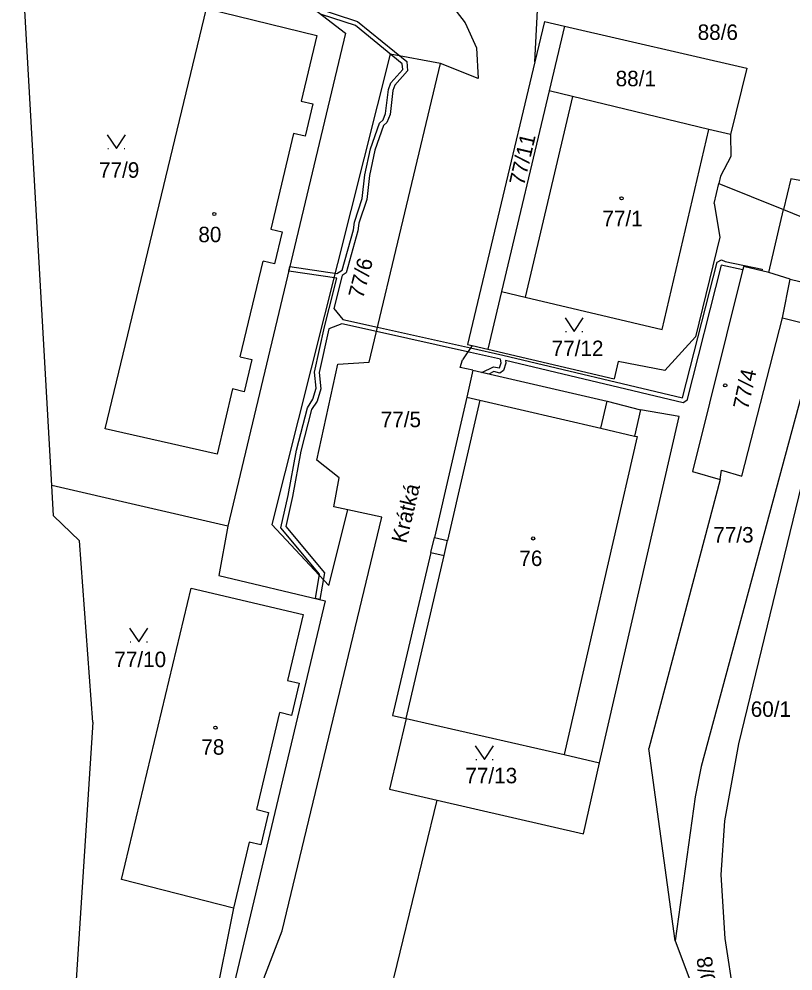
# Model space of a CAD drawing. Extents: x -670359 to -668019, y -978807 to -976674.
# Drawn here: x -670340.4 to -670255.4, y -977711.4 to -977606.8 of the extents above; entities that cross this region are included whole.
import ezdxf

# ---------------------------------------------------------------- set-up
doc = ezdxf.new("R2010")
doc.units = 0
for name, color, linetype in [('Hranice kat_území', 7, 'Continuous'), ('Hranice parcel', 7, 'Continuous'), ('Parcelní čísla', 7, 'Continuous'), ('Pop  PČ popisy', 7, 'Continuous'), ('Vnitřní kresba', 7, 'Continuous'), ('Věcná břemena k části', 7, 'Continuous'), ('Značky budov', 7, 'Continuous'), ('Značky kultur', 7, 'Continuous')]:
    doc.layers.add(name, color=color, linetype=linetype)

msp = doc.modelspace()

# ---------------------------------------------------------------- linework, layer by layer
at = {"layer": 'Hranice kat_území'}
for points in [[(-670336.85, -977658.05), (-670340.44, -977594.85)], [(-670336.66, -977661.37), (-670336.85, -977658.05)], [(-670333.8, -977664.11), (-670336.66, -977661.37)], [(-670332.34, -977684.03), (-670333.8, -977664.11)], [(-670332.34, -977684.03), (-670334.21, -977712.94)]]:
    msp.add_lwpolyline(points, dxfattribs=at)
at = {"layer": 'Hranice parcel'}
for points in [[(-670283.76, -977611.51), (-670283.19, -977600.11)], [(-670311.4, -977603.07), (-670304.57, -977608.35)], [(-670293.42, -977604.61), (-670291.41, -977607.22)], [(-670330.99, -977651.81), (-670319.86, -977605.66)], [(-670319.86, -977605.66), (-670307.72, -977608.63)], [(-670282.7, -977607.08), (-670283.76, -977611.51)], [(-670282.7, -977607.08), (-670280.5, -977607.59)], [(-670291.41, -977607.22), (-670290.19, -977609.96)], [(-670280.5, -977607.59), (-670282.2, -977614.71)], [(-670280.5, -977607.59), (-670260.47, -977612.22)], [(-670304.57, -977608.35), (-670317.49, -977662.51)], [(-670307.72, -977608.63), (-670309.43, -977615.83)], [(-670290.19, -977609.96), (-670289.99, -977613.35)], [(-670301.97, -977644.5), (-670294.13, -977611.68)], [(-670289.99, -977613.35), (-670294.13, -977611.68)], [(-670283.76, -977611.51), (-670291.18, -977642.54)], [(-670260.47, -977612.22), (-670262.27, -977619.5)], [(-670282.2, -977614.71), (-670287.43, -977636.75)], [(-670279.63, -977615.33), (-670282.2, -977614.71)], [(-670264.66, -977618.94), (-670279.63, -977615.33)], [(-670309.43, -977615.83), (-670308.17, -977616.13)], [(-670308.17, -977616.13), (-670309.02, -977619.68)], [(-670310.28, -977619.38), (-670312.79, -977629.87)], [(-670309.02, -977619.68), (-670310.28, -977619.38)], [(-670269.78, -977640.91), (-670264.66, -977618.94)], [(-670262.27, -977619.5), (-670264.66, -977618.94)], [(-670262.27, -977619.5), (-670262.23, -977621.89)], [(-670262.23, -977621.89), (-670263.37, -977624.05)], [(-670264.06, -977627.06), (-670263.56, -977624.87)], [(-670263.37, -977624.05), (-670263.56, -977624.87)], [(-670263.56, -977624.87), (-670256.44, -977627.73)], [(-670264.06, -977627.06), (-670263.45, -977630.78)], [(-670258.05, -977634.65), (-670256.44, -977627.73)], [(-670256.44, -977627.73), (-670253.29, -977629)], [(-670312.79, -977629.87), (-670311.52, -977630.18)], [(-670311.52, -977630.18), (-670312.36, -977633.7)], [(-670263.45, -977630.78), (-670266.1, -977641.73)], [(-670316.13, -977643.91), (-670313.63, -977633.4)], [(-670312.36, -977633.7), (-670313.63, -977633.4)], [(-670260.84, -977633.99), (-670266.45, -977656.5)], [(-670258.05, -977634.65), (-670260.84, -977633.99)], [(-670255.73, -977635.38), (-670258.05, -977634.65)], [(-670256.56, -977639.61), (-670255.73, -977635.38)], [(-670287.43, -977636.75), (-670288.94, -977643.07)], [(-670287.43, -977636.75), (-670284.82, -977637.36)], [(-670284.82, -977637.36), (-670269.78, -977640.91)], [(-670261.01, -977657.02), (-670256.56, -977639.61)], [(-670252.45, -977640.66), (-670265.48, -977688.9)], [(-670228.39, -977798.54), (-670235.68, -977780.88), (-670248.21, -977752.09), (-670257.66, -977728.06), (-670261.88, -977714.27), (-670262.87, -977707.81), (-670263.3, -977700.83), (-670262.9, -977694.87), (-670261.36, -977686.41), (-670250.36, -977641.2)], [(-670290.67, -977642.66), (-670291.73, -977644.25)], [(-670291.18, -977642.54), (-670290.67, -977642.66)], [(-670290.67, -977642.66), (-670288.94, -977643.07)], [(-670266.1, -977641.73), (-670269.49, -977645.42)], [(-670288.94, -977643.07), (-670275.07, -977646.34)], [(-670316.13, -977643.91), (-670314.87, -977644.21)], [(-670314.87, -977644.21), (-670315.71, -977647.74)], [(-670307.73, -977655.25), (-670305.41, -977644.71)], [(-670305.41, -977644.71), (-670301.97, -977644.5)], [(-670291.96, -977645.08), (-670291.73, -977644.25)], [(-670274.62, -977644.41), (-670275.07, -977646.34)], [(-670269.49, -977645.42), (-670274.62, -977644.41)], [(-670290.58, -977645.39), (-670291.96, -977645.08)], [(-670290.58, -977645.39), (-670291.25, -977648.36)], [(-670290.58, -977645.39), (-670275.82, -977648.8)], [(-670316.98, -977647.44), (-670318.69, -977654.62)], [(-670315.71, -977647.74), (-670316.98, -977647.44)], [(-670291.25, -977648.36), (-670294.8, -977663.76)], [(-670275.82, -977648.8), (-670272.15, -977649.75)], [(-670267.91, -977650.48), (-670272.15, -977649.75)], [(-670276.65, -977688.5), (-670267.91, -977650.48)], [(-670318.69, -977654.62), (-670330.99, -977651.81)], [(-670305.26, -977657.19), (-670307.73, -977655.25)], [(-670305.85, -977660.38), (-670305.26, -977657.19)], [(-670266.45, -977656.5), (-670263.41, -977657.4)], [(-670263.41, -977657.4), (-670263.25, -977656.36)], [(-670263.25, -977656.36), (-670261.01, -977657.02)], [(-670317.49, -977662.51), (-670336.85, -977658.05)], [(-670263.41, -977657.4), (-670271.23, -977686.94)], [(-670304.33, -977660.72), (-670305.85, -977660.38)], [(-670300.57, -977661.54), (-670304.33, -977660.72)], [(-670317.49, -977662.51), (-670318.48, -977667.94)], [(-670311.54, -977706.97), (-670300.57, -977661.54)], [(-670295.18, -977665.42), (-670294.8, -977663.76)], [(-670295.18, -977665.42), (-670299.39, -977683.32)], [(-670318.48, -977667.94), (-670306.8, -977670.72)], [(-670329.19, -977701.33), (-670321.52, -977669.31)], [(-670321.52, -977669.31), (-670309.21, -977672.2)], [(-670306.8, -977670.72), (-670317.87, -977717.22)], [(-670309.21, -977672.2), (-670310.94, -977679.47)], [(-670310.94, -977679.47), (-670309.66, -977679.77)], [(-670309.66, -977679.77), (-670310.51, -977683.31)], [(-670314.32, -977693.65), (-670311.78, -977683)], [(-670310.51, -977683.31), (-670311.78, -977683)], [(-670299.39, -977683.32), (-670297.92, -977683.65)], [(-670297.92, -977683.65), (-670299.73, -977691.42)], [(-670297.92, -977683.65), (-670280.54, -977687.61)], [(-670280.54, -977687.61), (-670276.65, -977688.5)], [(-670268.34, -977708.07), (-670271.23, -977686.94)], [(-670278.44, -977696.31), (-670276.65, -977688.5)], [(-670265.48, -977688.9), (-670266.14, -977692.25)], [(-670299.73, -977691.42), (-670294.49, -977692.62)], [(-670299.92, -977714.89), (-670294.49, -977692.62)], [(-670294.49, -977692.62), (-670278.44, -977696.31)], [(-670266.14, -977692.25), (-670268.34, -977708.07)], [(-670314.32, -977693.65), (-670313.04, -977693.96)], [(-670313.04, -977693.96), (-670313.89, -977697.52)], [(-670315.16, -977697.22), (-670316.89, -977704.46)], [(-670313.89, -977697.52), (-670315.16, -977697.22)], [(-670316.89, -977704.46), (-670329.19, -977701.33)], [(-670317.01, -977721.25), (-670311.54, -977706.97)], [(-670268.34, -977708.07), (-670252.01, -977751.62)]]:
    msp.add_lwpolyline(points, dxfattribs=at)
at = {"layer": 'Vnitřní kresba'}
for points in [[(-670299.65, -977610.68), (-670312.66, -977662.34)], [(-670294.13, -977611.68), (-670299.65, -977610.68)], [(-670279.63, -977615.33), (-670284.82, -977637.36)], [(-670255.65, -977624.35), (-670256.44, -977627.73)], [(-670252.06, -977625.01), (-670255.65, -977624.35)], [(-670255.73, -977635.38), (-670251.31, -977636.43)], [(-670256.56, -977639.61), (-670252.45, -977640.66)], [(-670289.82, -977648.69), (-670293.37, -977664.09)], [(-670291.25, -977648.36), (-670289.82, -977648.69)], [(-670289.82, -977648.69), (-670276.51, -977651.76)], [(-670276.51, -977651.76), (-670275.82, -977648.8)], [(-670272.15, -977649.75), (-670272.83, -977652.61)], [(-670276.51, -977651.76), (-670272.83, -977652.61)], [(-670272.51, -977652.68), (-670280.54, -977687.61)], [(-670272.83, -977652.61), (-670272.51, -977652.68)], [(-670306.39, -977669.02), (-670304.33, -977660.72)], [(-670312.66, -977662.34), (-670306.39, -977669.02)], [(-670294.8, -977663.76), (-670293.37, -977664.09)], [(-670293.75, -977665.75), (-670293.37, -977664.09)], [(-670295.18, -977665.42), (-670293.75, -977665.75)], [(-670297.92, -977683.65), (-670293.75, -977665.75)], [(-670316.89, -977704.46), (-670319.04, -977715.24)]]:
    msp.add_lwpolyline(points, dxfattribs=at)
at = {"layer": 'Věcná břemena k části'}
for p, q in [((-670308.39, -977605.4), (-670303.24, -977607.08)), ((-670303.48, -977607.52), (-670307.22, -977606.3)), ((-670303.24, -977607.08), (-670297.85, -977611.46)), ((-670298.33, -977611.72), (-670303.48, -977607.52)), ((-670299.59, -977613.8), (-670298.27, -977612.33)), ((-670298.27, -977612.33), (-670298.33, -977611.72)), ((-670297.85, -977611.46), (-670297.75, -977612.49)), ((-670297.75, -977612.49), (-670299.15, -977614.06)), ((-670299.86, -977614.55), (-670299.59, -977613.8)), ((-670299.15, -977614.06), (-670299.36, -977614.67)), ((-670300.16, -977617.17), (-670299.86, -977614.55)), ((-670299.36, -977614.67), (-670299.68, -977617.29)), ((-670300.45, -977617.88), (-670300.16, -977617.17)), ((-670299.68, -977617.29), (-670300.03, -977618.16)), ((-670301.82, -977621.06), (-670300.82, -977618.23)), ((-670300.38, -977618.51), (-670301.34, -977621.2)), ((-670300.82, -977618.23), (-670300.45, -977617.88)), ((-670300.03, -977618.16), (-670300.38, -977618.51)), ((-670302.43, -977623.92), (-670301.82, -977621.06)), ((-670301.34, -977621.2), (-670301.93, -977624)), ((-670302.73, -977626.53), (-670302.43, -977623.92)), ((-670301.93, -977624), (-670302.23, -977626.63)), ((-670303.57, -977629.12), (-670302.73, -977626.53)), ((-670302.23, -977626.63), (-670303.09, -977629.24)), ((-670304.95, -977634.4), (-670303.71, -977629.96)), ((-670303.23, -977630.06), (-670304.5, -977634.67)), ((-670303.71, -977629.96), (-670303.57, -977629.12)), ((-670303.09, -977629.24), (-670303.23, -977630.06)), ((-670263.74, -977633.52), (-670263.25, -977633.24)), ((-670263.25, -977633.24), (-670262.85, -977633.43)), ((-670310.68, -977633.98), (-670305.53, -977634.76)), ((-670267.54, -977648.4), (-670263.74, -977633.52)), ((-670263.3, -977633.84), (-670267.07, -977648.7)), ((-670260.93, -977634.35), (-670263.3, -977633.84)), ((-670262.85, -977633.43), (-670258.78, -977634.3)), ((-670260.84, -977633.99), (-670260.93, -977634.35)), ((-670258.82, -977634.47), (-670260.84, -977633.99)), ((-670258.78, -977634.3), (-670258.82, -977634.47)), ((-670305.52, -977635.27), (-670310.81, -977634.49)), ((-670306.35, -977638.61), (-670305.52, -977635.27)), ((-670304.93, -977634.97), (-670305.84, -977638.61)), ((-670305.53, -977634.76), (-670304.95, -977634.4)), ((-670304.5, -977634.67), (-670304.93, -977634.97)), ((-670306.87, -977640.61), (-670306.35, -977638.61)), ((-670305.84, -977638.61), (-670304.85, -977639.8)), ((-670307.97, -977645.61), (-670306.87, -977640.61)), ((-670304.97, -977640.29), (-670306.41, -977640.85)), ((-670301.17, -977641.14), (-670304.97, -977640.29)), ((-670304.85, -977639.8), (-670301.05, -977640.65)), ((-670306.41, -977640.85), (-670307.47, -977645.63)), ((-670291.15, -977643.38), (-670301.17, -977641.14)), ((-670301.05, -977640.65), (-670290.85, -977642.93)), ((-670287.54, -977644.18), (-670291.15, -977643.38)), ((-670290.85, -977642.93), (-670287.27, -977643.73)), ((-670287.27, -977643.73), (-670267.54, -977648.4)), ((-670287.67, -977645.13), (-670287.47, -977644.58)), ((-670287.47, -977644.58), (-670287.54, -977644.18)), ((-670286.95, -977644.6), (-670287.2, -977645.42)), ((-670267.49, -977648.95), (-670287.01, -977644.3)), ((-670287.01, -977644.3), (-670286.95, -977644.6)), ((-670307.78, -977647.37), (-670307.97, -977645.61)), ((-670307.47, -977645.63), (-670307.28, -977647.41)), ((-670289.59, -977645.62), (-670288.32, -977645.02)), ((-670288.81, -977645.8), (-670289.59, -977645.62)), ((-670288.26, -977645.54), (-670288.81, -977645.8)), ((-670288.32, -977645.02), (-670287.67, -977645.13)), ((-670287.61, -977645.7), (-670288.26, -977645.54)), ((-670287.2, -977645.42), (-670287.61, -977645.7)), ((-670308.15, -977648.56), (-670307.78, -977647.37)), ((-670307.28, -977647.41), (-670307.69, -977648.78)), ((-670308.76, -977649.5), (-670308.15, -977648.56)), ((-670307.69, -977648.78), (-670308.3, -977649.7)), ((-670267.07, -977648.7), (-670267.49, -977648.95)), ((-670309.96, -977654.18), (-670308.76, -977649.5)), ((-670308.3, -977649.7), (-670309.48, -977654.28)), ((-670310.86, -977659.15), (-670309.96, -977654.18)), ((-670309.48, -977654.28), (-670310.38, -977659.25)), ((-670311.68, -977662.7), (-670310.86, -977659.15)), ((-670310.38, -977659.25), (-670311.14, -977662.56)), ((-670311.14, -977662.56), (-670306.88, -977667.65)), ((-670307.42, -977667.79), (-670311.68, -977662.7)), ((-670307.88, -977670.46), (-670307.42, -977667.79)), ((-670306.88, -977667.65), (-670307.39, -977670.58))]:
    msp.add_line(p, q, dxfattribs=at)
for points in [[(-670310.81, -977634.49), (-670310.68, -977633.98)], [(-670307.39, -977670.58), (-670307.88, -977670.46)]]:
    msp.add_lwpolyline(points, dxfattribs=at)
at = {"layer": 'Značky budov'}
for centre in [(-670274.24, -977626.5), (-670318.99, -977628.22), (-670262.85, -977647.05), (-670283.95, -977663.86), (-670318.86, -977684.65)]:
    msp.add_circle(centre, 0.175, dxfattribs=at)
at = {"layer": 'Značky kultur'}
for p, q in [((-670330.7, -977621.03), (-670330.6, -977621.03)), ((-670328.9, -977621.03), (-670328.8, -977621.03)), ((-670280.4, -977641.14), (-670280.3, -977641.14)), ((-670278.6, -977641.14), (-670278.5, -977641.14)), ((-670328.24, -977675.23), (-670328.14, -977675.23)), ((-670326.44, -977675.23), (-670326.34, -977675.23)), ((-670290.26, -977688.16), (-670290.16, -977688.16)), ((-670288.46, -977688.16), (-670288.36, -977688.16))]:
    msp.add_line(p, q, dxfattribs=at)
for points in [[(-670330.75, -977619.53), (-670329.75, -977621.03), (-670328.75, -977619.53)], [(-670280.45, -977639.64), (-670279.45, -977641.14), (-670278.45, -977639.64)], [(-670328.29, -977673.73), (-670327.29, -977675.23), (-670326.29, -977673.73)], [(-670290.31, -977686.66), (-670289.31, -977688.16), (-670288.31, -977686.66)]]:
    msp.add_lwpolyline(points, dxfattribs=at)
for centre in [(-670274.24, -977626.5), (-670318.99, -977628.22), (-670262.85, -977647.05), (-670283.95, -977663.86), (-670318.86, -977684.65)]:
    msp.add_circle(centre, 0.175, dxfattribs=at)

# ---------------------------------------------------------------- texts
at = {"layer": 'Parcelní čísla'}
for s, p in [('88/6', (-670265.88, -977609.1)), ('88/1', (-670274.89, -977614.19)), ('77/9', (-670331.65, -977624.24)), ('77/1', (-670276.35, -977629.57)), ('80', (-670320.74, -977631.32)), ('77/12', (-670281.92, -977643.83)), ('77/5', (-670300.7, -977651.64)), ('77/3', (-670264.16, -977664.31)), ('76', (-670285.47, -977666.89)), ('77/10', (-670329.97, -977678)), ('60/1', (-670260.05, -977683.46)), ('78', (-670320.41, -977687.62)), ('77/13', (-670291.4, -977690.76))]:
    msp.add_text(s, height=1.7, dxfattribs=at).set_placement(p)
for s, rotation, p in [('77/11', 76.7837, (-670284.96, -977625.18)), ('77/6', 75.3356, (-670302.65, -977637.6)), ('77/4', 77.4825, (-670260.36, -977649.79)), ('60/8', 99.1577, (-670263.65, -977714.04))]:
    msp.add_text(s, height=1.7, rotation=rotation, dxfattribs=at).set_placement(p)
at = {"layer": 'Pop  PČ popisy'}
msp.add_text('Krátká', height=1.7, rotation=76.5396, dxfattribs=at).set_placement((-670297.9, -977664.48))

doc.saveas('drawing.dxf')
